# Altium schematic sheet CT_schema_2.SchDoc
size 316 x 185 mm
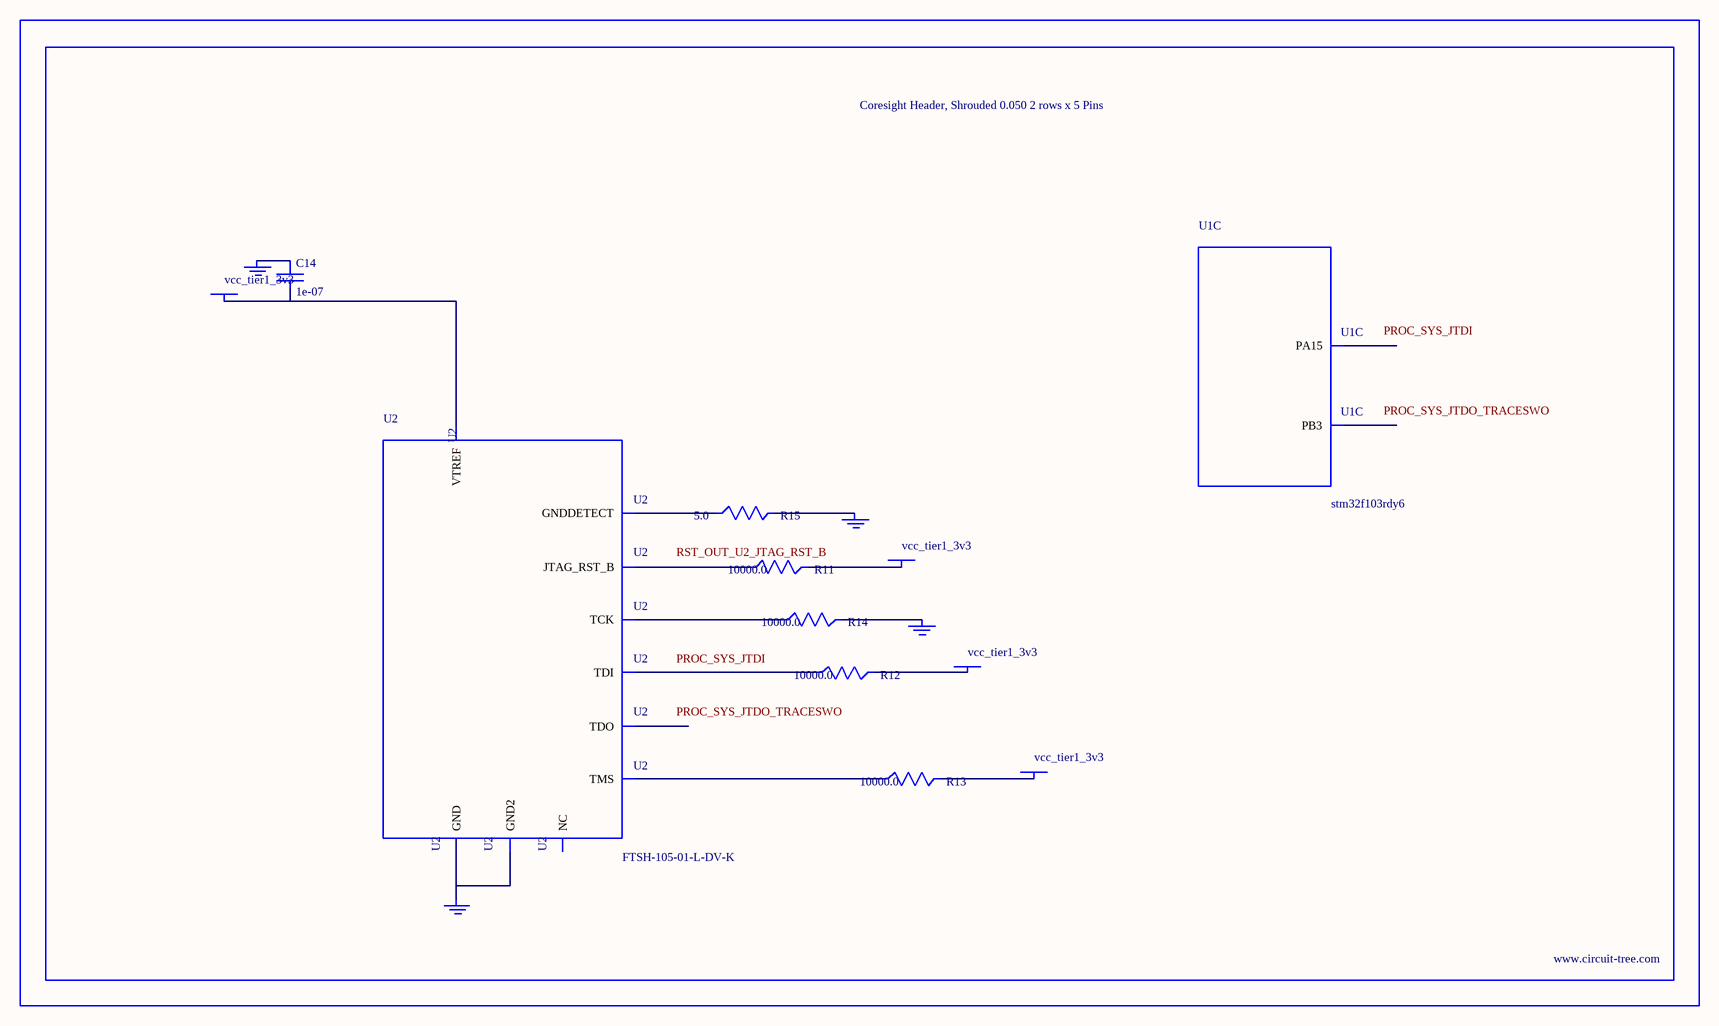
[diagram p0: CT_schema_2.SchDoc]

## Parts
BORDER1  (no value)
C14  1e-07  [C0402]
GND_INSTANCE_1_0  (no value)
GND_INSTANCE_1_1  (no value)
GND_INSTANCE_1_2  (no value)
GND_INSTANCE_1_3  (no value)
POWER_INSTANCE_1_0  vcc_tier1_3v3
POWER_INSTANCE_1_1  vcc_tier1_3v3
POWER_INSTANCE_1_2  vcc_tier1_3v3
POWER_INSTANCE_1_3  vcc_tier1_3v3
R11  10000.0  [R0603]
R12  10000.0  [R0603]
R13  10000.0  [R0603]
R14  10000.0  [R0603]
R15  5.0  [R0603]
U1  stm32f103rdy6  [WLCSP64]  (part C of 7)
U2  FTSH-105-01-L-DV-K  [SAMTEC_FTSH-105-01-L-DV-K]

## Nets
NetC14_1: C14.1 GND_INSTANCE_1_0.0(GND)
NetC14_2: C14.2 POWER_INSTANCE_1_0.0(PWR) U2.1(VTREF)
NetGND_INSTANCE_1_1_0: GND_INSTANCE_1_1.0(GND) R14.2
NetGND_INSTANCE_1_2_0: GND_INSTANCE_1_2.0(GND) R15.2
NetGND_INSTANCE_1_3_0: GND_INSTANCE_1_3.0(GND) U2.3(GND) U2.5(GND2)
NetPOWER_INSTANCE_1_1_0: POWER_INSTANCE_1_1.0(PWR) R13.2
NetPOWER_INSTANCE_1_2_0: POWER_INSTANCE_1_2.0(PWR) R12.2
NetPOWER_INSTANCE_1_3_0: POWER_INSTANCE_1_3.0(PWR) R11.2
NetR11_1: R11.1 U2.10(JTAG_RST_B)
NetR12_1: R12.1 U2.8(TDI)
NetR13_1: R13.1 U2.2(TMS)
NetR14_1: R14.1 U2.4(TCK)
NetR15_1: R15.1 U2.9(GNDDETECT)

Not connected (* = marked no-connect by the designer): U1 A4(PB3) C3(PA15); U2 6(TDO) 7(NC)

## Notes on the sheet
- Labels drawn without touching a wire or pin: PROC_SYS_JTDI, PROC_SYS_JTDO_TRACESWO, RST_OUT_U2_JTAG_RST_B

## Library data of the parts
BORDER1 = BORDER_PAGE1
C14 = C0402C104K3RACTU
GND_INSTANCE_1_0-GND_INSTANCE_1_3 = GND
POWER_INSTANCE_1_0-POWER_INSTANCE_1_3 = PWR
R11-R14 = RC0603JR-0710KL
R15 = ERJ-3GEYJ5R1V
